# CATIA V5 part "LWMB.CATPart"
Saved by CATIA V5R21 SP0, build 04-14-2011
Part number: LWMB.SLDPRT
Bounding box of the stored display mesh (mm): x -1.375 to 1.375, y -1 to 1, z -0.25 to 0.45
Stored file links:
  C:\Users\user\Desktop\CATIA文件\0-最新文件(2025.3月之前的慎用)\LWMB\LWMB.CATPart
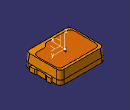
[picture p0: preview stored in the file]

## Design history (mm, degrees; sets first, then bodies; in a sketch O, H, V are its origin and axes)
AxisSystem1: origin (0, 0, 0.45), X (0, -1, 0), Y (1, 0, 0), Z (0, 0, 1)
Set1
  DatumSurface1 to DatumSurface42
  Line1 to Line3: stored without definition
  Circle1: stored without definition
  Line4: stored without definition
  Circle2: stored without definition
  Line5: stored without definition
  Circle3: stored without definition
  Line6: stored without definition
  Circle4: stored without definition
  Line7: stored without definition
  Circle5: stored without definition
  Line8: stored without definition
  Circle6: stored without definition
  Line9 to Line13: stored without definition
  Circle7: stored without definition
  Line14: stored without definition
  Circle8: stored without definition
  Circle9: stored without definition
  Line15: stored without definition
  Circle10: stored without definition
  Line16: stored without definition
  Circle11: stored without definition
  Line17 to Line19: stored without definition
  Circle12: stored without definition
  Line20: stored without definition
  Circle13: stored without definition
  Line21: stored without definition
  Circle14: stored without definition
  Line22: stored without definition
  Circle15: stored without definition
  Line23 to Line35: stored without definition
  Circle16: stored without definition
  Line36 to Line38: stored without definition
  Circle17: stored without definition
  Line39 to Line43: stored without definition
  Circle18: stored without definition
  Line44 to Line46: stored without definition
  Circle19: stored without definition
  Line47: stored without definition
  Line48: stored without definition
  Circle20: stored without definition
  Line49 to Line51: stored without definition
  Circle21: stored without definition
  Line52 to Line55: stored without definition
  Circle22: stored without definition
  Line56 to Line58: stored without definition
  Circle23: stored without definition
  Line59 to Line62: stored without definition
  Circle24: stored without definition
  Line63 to Line65: stored without definition
  Circle25: stored without definition
  Line66 to Line69: stored without definition
  Circle26: stored without definition
  Circle27: stored without definition
  Line70: stored without definition
  Circle28: stored without definition
  Circle29: stored without definition
  Line71: stored without definition
  Circle30: stored without definition
  Circle31: stored without definition
  Line72: stored without definition
  Circle32: stored without definition
  Line73 to Line88: stored without definition
  DatumSurface43 to DatumSurface131
  DatumCurve1
  Line89: stored without definition
  DatumCurve2
  Line90: stored without definition
  DatumCurve3
  Line91: stored without definition
  DatumCurve4
  Line92: stored without definition
  DatumCurve5
  Line93: stored without definition
  DatumCurve6
  Line94: stored without definition
  Line95: stored without definition
  DatumCurve7
  Line96: stored without definition
  DatumCurve8
  Line97: stored without definition
  DatumCurve9
  Line98: stored without definition
  DatumCurve10
  Line99: stored without definition
  DatumCurve11
  Line100: stored without definition
  DatumCurve12
  Line101 to Line132: stored without definition
  DatumCurve13 to DatumCurve16
  Circle33: stored without definition
  Line133: stored without definition
  Circle34: stored without definition
  Line134: stored without definition
  Line135: stored without definition
  Circle35: stored without definition
  Line136: stored without definition
  Circle36: stored without definition
  Line137: stored without definition
  Line138: stored without definition
  Circle37: stored without definition
  Line139: stored without definition
  Circle38: stored without definition
  Circle39: stored without definition
  Line140: stored without definition
  Circle40: stored without definition
  Line141: stored without definition
  Circle41: stored without definition
  Line142: stored without definition
  Circle42: stored without definition
  Line143: stored without definition
  Line144: stored without definition
  Circle43: stored without definition
  Line145: stored without definition
  Circle44: stored without definition
  Circle45: stored without definition
  Line146: stored without definition
  Line147: stored without definition
  Circle46: stored without definition
  Line148: stored without definition
  Circle47: stored without definition
  Line149: stored without definition
  Circle48: stored without definition
  Line150: stored without definition
  Circle49: stored without definition
  Line151 to Line154: stored without definition
  DatumCurve17 to DatumCurve20
  Line155: stored without definition
  Circle50: stored without definition
  Line156: stored without definition
  Circle51: stored without definition
  Line157 to Line161: stored without definition
  Circle52: stored without definition
  Line162: stored without definition
  Line163: stored without definition
  Circle53: stored without definition
  Line164 to Line168: stored without definition
  Circle54: stored without definition
  Line169: stored without definition
  Circle55: stored without definition
  Circle56: stored without definition
  Line170: stored without definition
  Line171: stored without definition
  Circle57: stored without definition
  Line172: stored without definition
  Line173: stored without definition
  Circle58: stored without definition
  Line174 to Line185: stored without definition
  Circle59: stored without definition
  Line186 to Line189: stored without definition
  Circle60: stored without definition
  Line190 to Line195: stored without definition
  Circle61: stored without definition
  Line196 to Line199: stored without definition
  Circle62: stored without definition
  Line200 to Line202: stored without definition
  Circle63: stored without definition
  Line203: stored without definition
  Circle64: stored without definition
  Circle65: stored without definition
  Line204: stored without definition
  Circle66: stored without definition
  Line205 to Line220: stored without definition
  Circle67: stored without definition
  Circle68: stored without definition
  Line221: stored without definition
  Line222: stored without definition
  Circle69: stored without definition
  Line223: stored without definition
  Circle70: stored without definition
  Line224: stored without definition
  Circle71: stored without definition
  Line225 to Line236: stored without definition
  Circle72: stored without definition
  Line237: stored without definition
  Circle73: stored without definition
  Line238: stored without definition
  Circle74: stored without definition
  Line239 to Line241: stored without definition
  Circle75: stored without definition
  Line242 to Line247: stored without definition
  Circle76: stored without definition
  Line248 to Line254: stored without definition
  Circle77: stored without definition
  Line255 to Line258: stored without definition
  Circle78: stored without definition
  Circle79: stored without definition
  Line259 to Line261: stored without definition
  Circle80: stored without definition
  Line262 to Line265: stored without definition
  Circle81: stored without definition
  Line266: stored without definition
  Circle82: stored without definition
  Line267 to Line288: stored without definition
  DatumSurface132 to DatumSurface171
  Circle83: stored without definition
  Line289: stored without definition
  Circle84: stored without definition
  Line290: stored without definition
  Circle85: stored without definition
  Line291 to Line302: stored without definition
  Circle86: stored without definition
  Circle87: stored without definition
  Line303: stored without definition
  Circle88: stored without definition
  Line304 to Line315: stored without definition
  Circle89: stored without definition
  Line316: stored without definition
  Circle90: stored without definition
  Line317 to Line319: stored without definition
  Circle91 to Circle93: stored without definition
  Line320: stored without definition
  Circle94: stored without definition
  Line321 to Line323: stored without definition
  Circle95: stored without definition
  Line324: stored without definition
  Circle96: stored without definition
  Line325 to Line327: stored without definition
  Circle97: stored without definition
  Line328: stored without definition
  Circle98: stored without definition
  Line329 to Line331: stored without definition
  Circle99: stored without definition
  Circle100: stored without definition
  Line332: stored without definition
  Circle101: stored without definition
  Circle102: stored without definition
  Line333 to Line336: stored without definition
  Circle103: stored without definition
  Circle104: stored without definition
  Line337 to Line340: stored without definition
  Circle105: stored without definition
  Line341: stored without definition
  Circle106: stored without definition
  Line342 to Line352: stored without definition
  Circle107: stored without definition
  Line353: stored without definition
  Circle108: stored without definition
  Line354 to Line376: stored without definition
  Point1 "几何中心（测试原点）": type Between, FirstPoint vertex [face of DatumSurface56], SecondPoint vertex [face of DatumSurface52], Ratio 0.5
  Point2: (-0.0138, -0.0249, -0.1294), relative to Point1, in AxisSystem1
Body1 (main body)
